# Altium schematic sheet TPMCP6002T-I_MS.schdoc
size 127 x 101 mm
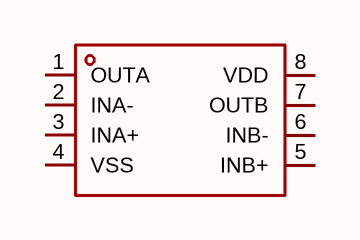
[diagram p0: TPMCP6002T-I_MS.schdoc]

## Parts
U?  tpmcp6002t-i/ms  [MSOP-8_L3.0-W3.0-P0.65-LS4.9-BL]  (value not drawn)

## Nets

Not connected (* = marked no-connect by the designer): U? 1(OUTA) 2(INA-) 3(INA+) 4(VSS) 5(INB+) 6(INB-) 7(OUTB) 8(VDD)

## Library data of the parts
U? = tpmcp6002t-i/ms: 放大器数:2;轨到轨:轨到轨输入,轨到轨输出;增益带宽积(GBW):1MHz;输入失调电压(Vos):5mV;压摆率(SR):600V/ms;输入偏置电流(Ib):10pA;; Manufacturer: TECH PUBLIC(台舟); AddInBom: yes; ModelId: bedc0aeebe0a475e87aaac88bd02a14b; ModelName: MSOP-8_L3.0-W3.0-H1.1-LS4.9-P0.65; ModelTransform: 118.11,192.913,0,0,0,0,0,0,0; Number of Channels: 2; Gain Bandwidth Product: 1MHz; Vos - Input Offset Voltage: 5mV; Input Offset Voltage Drift(Vos TC): 2uV/℃; Ib - Input Bias Current: 10pA; Input Voltage Noise Density: 20nV/√Hz@10kHz; Common Mode Rejection Ratio(CMRR): 75dB; Quiescent Current: 110uA; Output Current: 20mA; Single supply: 1.8V~5.5V; Dual Supply: -2.75V~-900mV；900mV~2.75V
